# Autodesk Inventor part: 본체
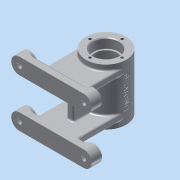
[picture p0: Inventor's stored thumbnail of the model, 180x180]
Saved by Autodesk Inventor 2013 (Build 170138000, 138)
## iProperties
Created: 2015-11
Part Number: 본체
Material: 알루미늄 6061
Document SubType Name: Modeling
Designer: a
Density: 2.71 g/cm^3
Mass: 358.636 g
Surface Area: 458.756 cm^2
Volume: 132.338 cm^3
Author: a
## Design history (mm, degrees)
sketch "스케치1"
  geometry: C1 r 25 at (0, 0); 1 further point
  constraints: 1 centre point, 1 coincident
  dimensions: "d0" = 50 diameter of C1
extrude "돌출1" new body sketch "스케치1" stored distance "d1" = 70; taper "d2" = 0 deg
sketch "스케치2"
  geometry: C1 r 21 at (0, 0); 1 further point
  constraints: 1 centre point, 1 coincident
  dimensions: "d3" = 42 diameter of C1
extrude "돌출2" cut sketch "스케치2" stored distance "d4" = 42; taper "d5" = 0 deg
node "작업 평면1"
sketch "스케치3"
  geometry: L1 (40, 20)-(-40, 20); L2 (-50, 30)-(-50, 30); L3 (-40, 40)-(40, 40); L4 (50, 30)-(50, 30); A1 r 10 centre (40, 30) between (40, 20) and (50, 30); A2 r 10 centre (40, 30) between (50, 30) and (40, 40); A3 r 10 centre (-40, 30) between (-40, 40) and (-50, 30); A4 r 10 centre (-40, 30) between (-50, 30) and (-40, 20); 5 further points
  constraints: 8 end point, 8 point on circle, 8 tangent, 6 point on line, 4 centre point, 3 equal radius, 2 parallel, 1 horizontal, 1 midpoint, 1 perpendicular, 1 vertical alignment
  dimensions: "d7" = 100 distance of point (-50, 40) point (50, 40); "d8" = 20 distance of point (-50, 20) point (-50, 40); "d9" = 40 distance from line of point (0, 0) L3; "d10" = 10 radius of A1
extrude "돌출3" join sketch "스케치3" distance "d11" = 10; taper "d12" = 0 deg
sketch "스케치4"
  geometry: C1 r 10 at (-40, -30); C2 r 10 at (40, -30); A1 r 10 centre (-40, -30) between (-40, -20) and (-40, -40) reference; A2 r 10 centre (40, -30) between (40, -40) and (40, -20) reference; 1 further point
  constraints: 2 centre point, 2 coincident
  dimensions: "d13" = 20 diameter of C1; "d14" = 20 diameter of C2
extrude "돌출4" join sketch "스케치4" distance "d15" = 3; taper "d16" = 0 deg
sketch "스케치5"
  geometry: L1 (-25, -20)-(25, -20); L2 (25, -20)-(25, -28); L3 (25, -28)-(-25, -28); L4 (-25, -28)-(-25, -20); 2 further points
  constraints: 8 end point, 2 parallel, 1 horizontal, 1 midpoint, 1 perpendicular, 1 vertical alignment
  dimensions: "d17" = 50 distance of L2.end L3.end; "d18" = 8 distance of L1.end L2.end; "d19" = 20 distance from line of point (0, 0) L1
extrude "돌출5" join sketch "스케치5" stored distance "d20" = 3; taper "d21" = 0 deg
sketch "스케치6"
  geometry: L1 (-45, 20)-(-45, -20); L2 (-21, -21)-(21, -21) reference; L3 (21, -21)-(21, 21) reference; L4 (21, 21)-(-21, 21) reference; L5 (-21, 21)-(-21, -21) reference; L6 (25, 35)-(25, -35) reference; L7 (25, -35)-(-25, -35) reference; L8 (-25, -35)-(-25, -28) reference; L9 (-25, -28)-(-58, -28) reference; L10 (-58, -28)-(-58, -40) reference; L11 (-58, -40)-(-68, -40) reference; L12 (-68, -40)-(-68, -20) reference; L13 (-68, -20)-(-25, -20) reference; L14 (-25, -20)-(-25, 20) reference; L15 (-25, 20)-(-68, 20) reference; L16 (-68, 20)-(-68, 40) reference; L17 (-68, 40)-(-58, 40) reference; L18 (-58, 40)-(-58, 28) reference; L19 (-58, 28)-(-25, 28) reference; L20 (-25, 28)-(-25, 35) reference; L21 (-25, 35)-(25, 35) reference; 2 further points
  constraints: 2 end point, 2 point on line, 1 horizontal alignment, 1 midpoint, 1 vertical
  dimensions: "d22" = 20 distance between parallel lines of L8 L1
feature "리브1" sketch "스케치6" dims "d23" = 1, "d24" = 8, "d25" = 0, "d26" = 0, "d27" = 1, "d28" = 1
sketch "스케치7"
  geometry: L1 (-12, 6.5)-(-28, 6.5); L2 (-31.5, 10)-(-31.5, 10); L3 (-28, 13.5)-(-12, 13.5); L4 (-8.5, 10)-(-8.5, 10); L5 (-8.5, 6.5)-(-31.5, 13.5); L6 (-31.5, 6.5)-(-8.5, 13.5); L7 (20, -23)-(0, -23) reference; A1 r 3.5 centre (-28, 10) between (-28, 13.5) and (-31.5, 10); A2 r 3.5 centre (-28, 10) between (-31.5, 10) and (-28, 6.5); A3 r 3.5 centre (-12, 10) between (-12, 6.5) and (-8.5, 10); A4 r 3.5 centre (-12, 10) between (-8.5, 10) and (-12, 13.5); 3 further points
  constraints: 12 end point, 8 point on circle, 8 point on line, 8 tangent, 4 centre point, 3 equal radius, 3 midpoint, 2 parallel, 1 horizontal, 1 perpendicular, 1 vertical alignment
  dimensions: "d29" = 23 distance of L5.end L6.end; "d30" = 7 distance of L6.start L5.end; "d31" = 33 distance from line of L7 point (-20, 10); "d32" = 3.5 radius of A1
extrude "돌출6" cut sketch "스케치7" stored distance "d33" = 3; taper "d34" = 0 deg
node "작업 평면2"
sketch "스케치8"
  geometry: C1 r 5 at (0, 0); 1 further point
  constraints: 1 centre point, 1 coincident
  dimensions: "d36" = 10 diameter of C1
extrude "돌출7" join sketch "스케치8" stored distance "d37" = 3; taper "d38" = 0 deg
sketch "스케치9"
  geometry: C1 r 5 at (0, 0) reference
hole "구멍1" sketch "스케치9" at (0, 0) diameter "d39" = 5.188; stored, may be unused: countersink angle "d43" = 90 deg, drill point angle "d45" = 118 deg; dims "d40" = 30, "d41" = 4, "d42" = 2, "d44" = 8
sketch "스케치10"
  geometry: C1 r 25 at (0, 0) reference
hole "구멍2" sketch "스케치10" at (0, 0) diameter "d46" = 28; stored, may be unused: countersink angle "d50" = 90 deg, drill point angle "d52" = 118 deg; dims "d47" = 6, "d48" = 32, "d49" = 12, "d51" = 8
sketch "스케치11"
  geometry: C1 r 16 at (0, 0) reference; 1 further point
  constraints: 1 vertical alignment
  dimensions: "d53" = 20 distance of point (0, 20) C1.centre
hole "구멍3" sketch "스케치11" at (0, 20) diameter "d54" = 3.242; stored, may be unused: countersink angle "d58" = 90 deg, drill point angle "d60" = 118 deg; dims "d55" = 8, "d56" = 10, "d57" = 12, "d59" = 10
sketch "스케치12"
  geometry: L1 (0, 0)-(-14, -24.249); L2 (0, 0)-(28, 0)
  constraints: 4 end point, 1 equal length, 1 horizontal
  dimensions: "d64" = 28 distance of L1.start L1.end; "d65" = 120 deg angle of L1 L2
node "작업 평면3"
sketch "스케치13"
  geometry: C1 r 6 at (0, 0); 1 further point
  constraints: 1 centre point, 1 coincident
  dimensions: "d66" = 12 diameter of C1
extrude "돌출8" join sketch "스케치13" stored distance "d67" = 3; taper "d68" = 0 deg
sketch "스케치14"
  geometry: C1 r 6 at (0, 0) reference
hole "구멍4" sketch "스케치14" at (0, 0) diameter "d69" = 5.188; stored, may be unused: countersink angle "d73" = 90 deg, drill point angle "d75" = 0 deg; dims "d70" = 30, "d71" = 10, "d72" = 12, "d74" = 10
fillet "모깎기1" dims "d76" = 2
fillet "모깎기2" dims "d77" = 2
node "작업 평면4"
sketch "스케치15"
  geometry: L1 (-25, -35)-(-25, 35) reference; L2 (-25, -35)-(25, -35) reference; L3 (25, 35)-(-25, 35) reference; L4 (25, -35)-(25, 35) reference; 2 further points
  constraints: 1 other
  dimensions: "d79" = 35 distance from line of point (0, 0) L2; "d80" = 25 distance from line of L1 point (0, 0); "d96" = 25 distance from line of L4 point (0, 0) (derived); "d97" = 35 distance from line of L3 point (0, 0) (derived)
feature "엠보싱1" sketch "스케치15" dims "d7" = 100, "d8" = 20, "d9" = 40, "d10" = 10, "d81" = 0.5, "d82" = 0
sketch "스케치16"
  geometry: C1 r 10 at (0, 0) reference; C2 r 10 at (0, 60) reference; C3 r 10 at (80, 60) reference; C4 r 10 at (80, 0) reference; 5 further points
  constraints: 4 coincident
hole "구멍5" sketch "스케치16" at (0, 0), (0, 60), (80, 0), (80, 60) diameter "d83" = 6; stored, may be unused: countersink angle "d87" = 90 deg, drill point angle "d89" = 0 deg; dims "d84" = 30, "d85" = 12, "d86" = 4, "d88" = 10
fillet "모깎기3" dims "d90" = 0.3, "d91" = 3
chamfer "모따기1" distance "d92" = 1; stored, may be unused: second distance "d93" = 2, angle "d94" = 45 deg
fillet "모깎기4" dims "d95" = 3
node "솔리드1"
mirror "대칭1"
mirror "대칭2"
mirror "대칭3"
pattern_circular "원형 패턴1" dims angle "d62" = 360 deg
mirror "대칭4"
node "투영된 루프1"
node "투영된 루프2"
node "투영된 루프3"
node "절단 모서리 투영1"
other parameters: "d6" = -68, "d35" = 28, "d78" = 25
